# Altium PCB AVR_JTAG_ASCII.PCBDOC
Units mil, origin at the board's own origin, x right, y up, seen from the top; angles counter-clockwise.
Board outline 2025 x 2150 mil, 2 copper layers (Top Layer, Bottom Layer); 21 components, 27 nets, 110 pads, 2 vias.
Unrouted connection lines stored in the file: 1.
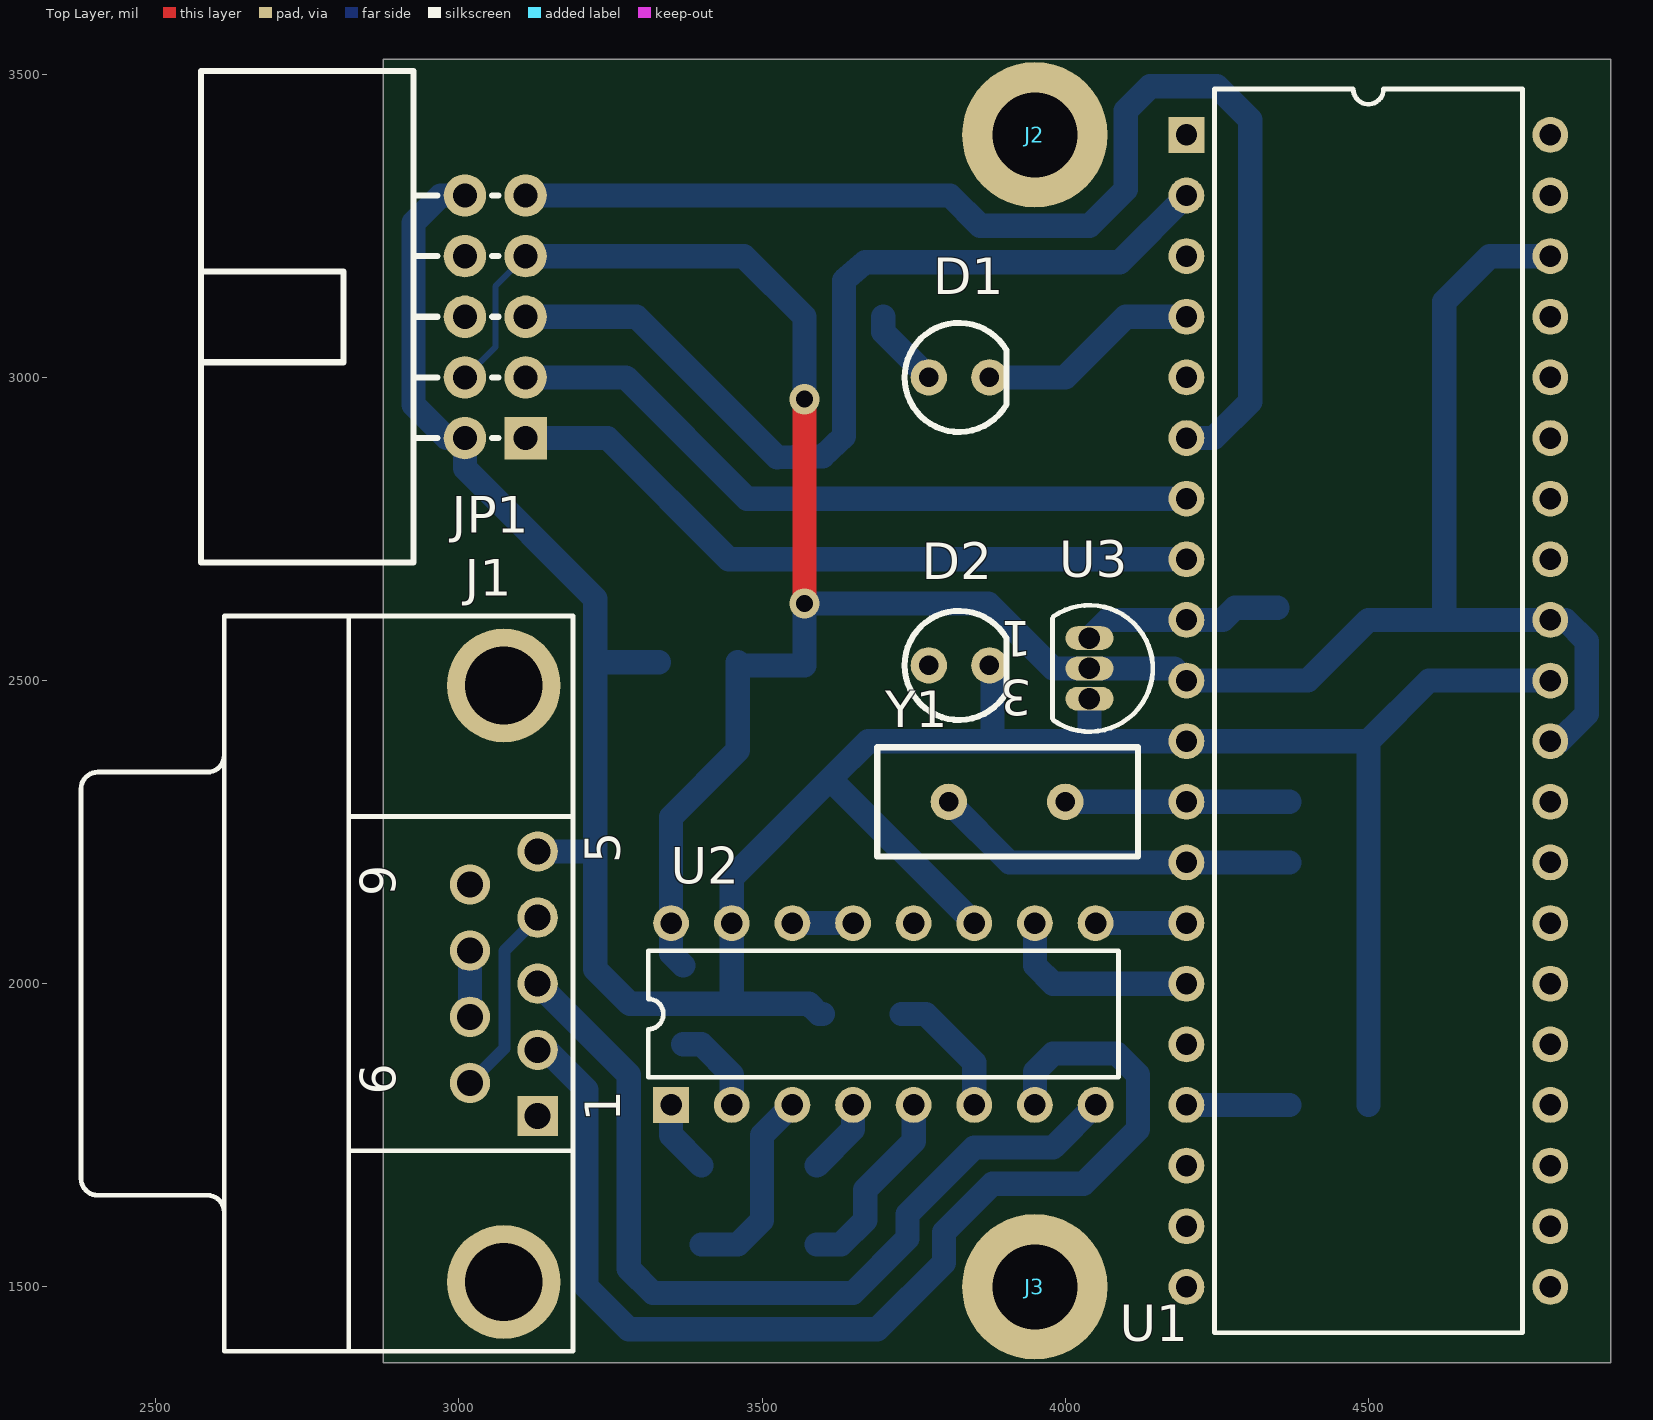
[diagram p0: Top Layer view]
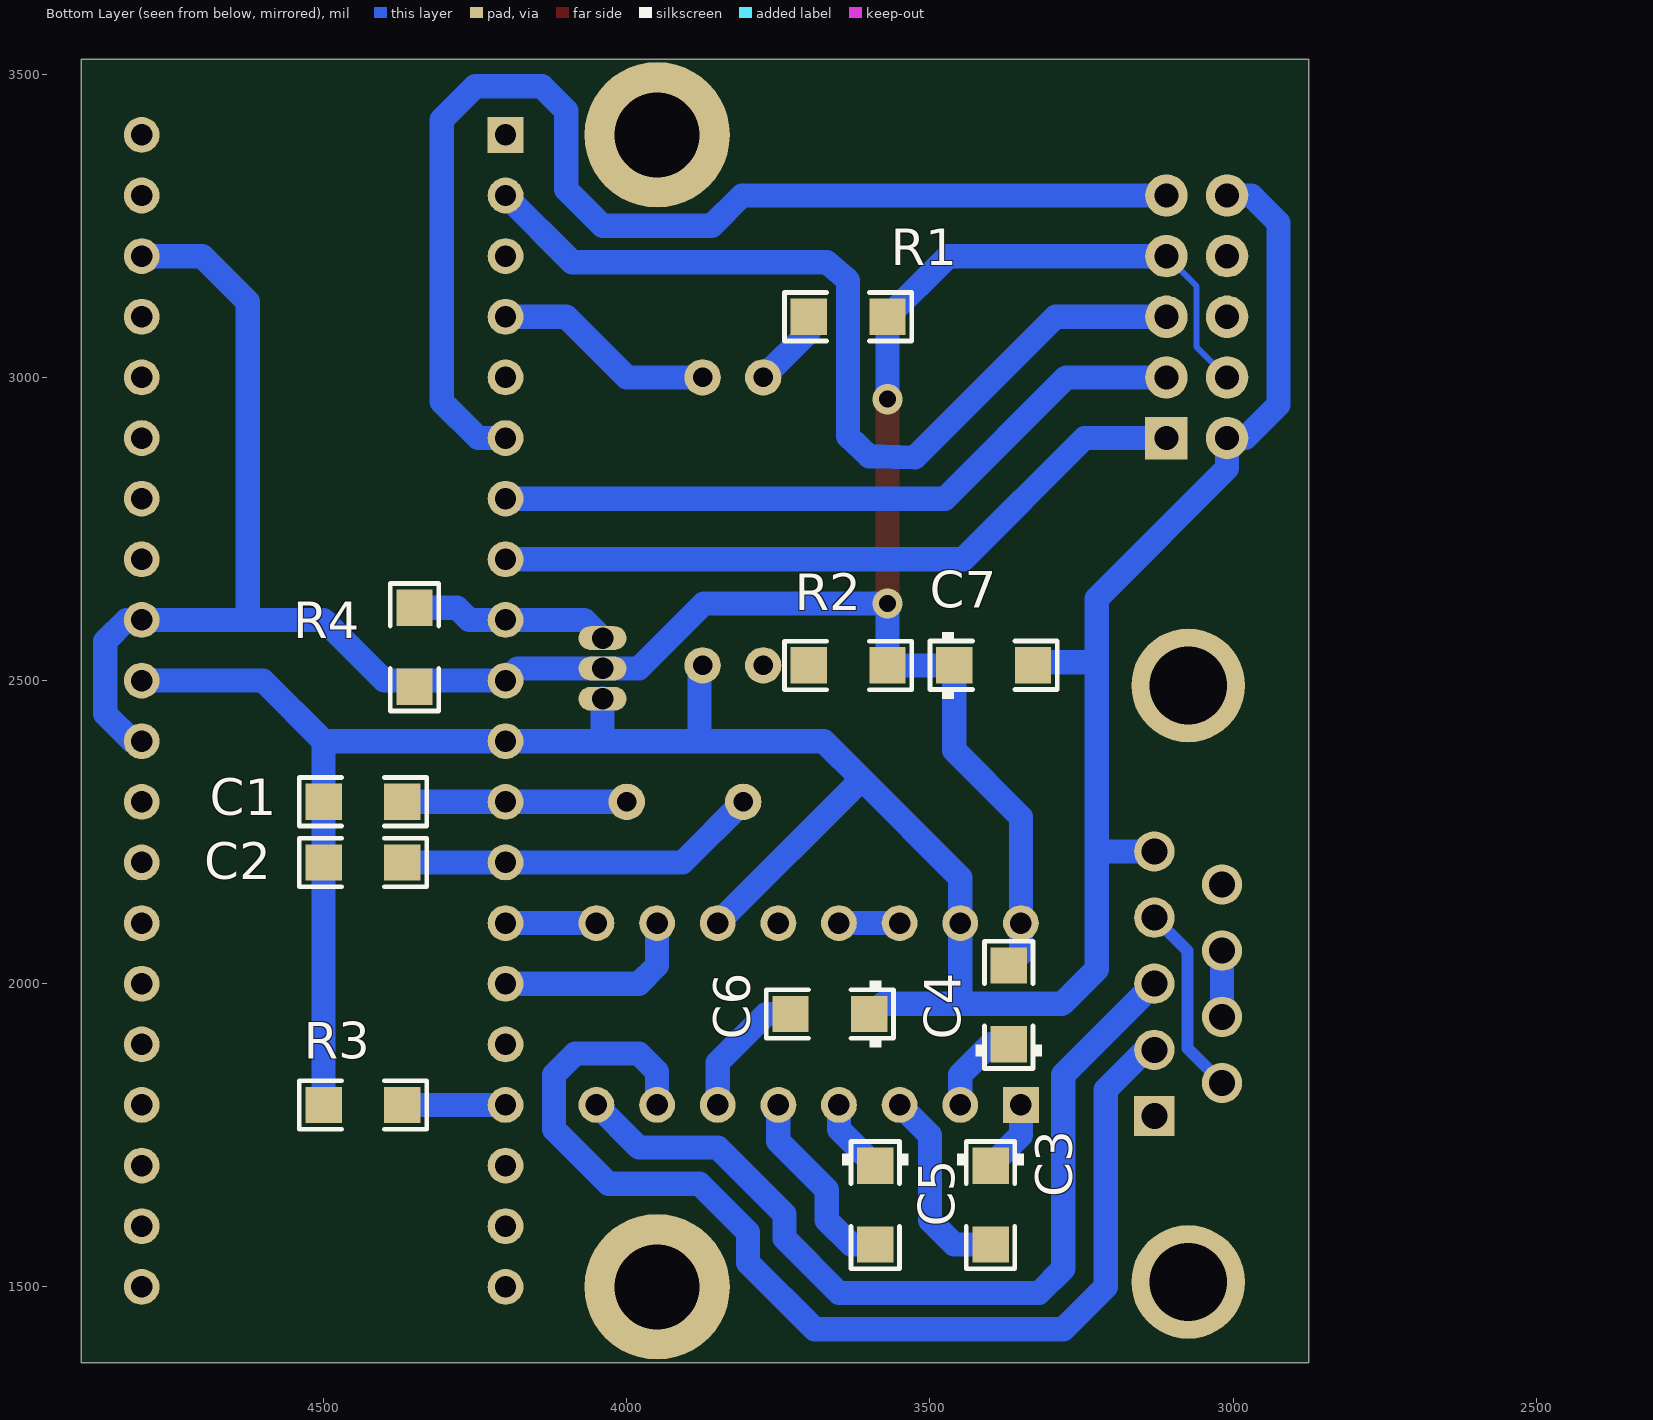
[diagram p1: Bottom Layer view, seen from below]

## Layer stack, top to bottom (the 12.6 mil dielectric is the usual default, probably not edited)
Top Layer: signal copper 1.4
Dielectric: dielectric 12.6, FR-4, Dk 4.8
Bottom Layer: signal copper 1.4

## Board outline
2875,1375 2875,3525 4900,3525 4900,1375

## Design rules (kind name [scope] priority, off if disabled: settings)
Clearance [All] p1: scope1count=1 scope1_0_kind=Board scope1_0_value=Board scope2count=1 scope2_0_kind=Board scope2_0_value=Board commentlength=0 planeconnectstyle=Relief reliefexpansion=20 reliefentries=4 reliefconductorwidth=10 reliefairgap="10mil / RECORD=DXPRule" gap=10
ComponentClearance [All] p1: scope1count=1 scope1_0_kind=Board scope1_0_value=Board scope2count=1 scope2_0_kind=Board scope2_0_value=Board commentlength=0 enforce="TRUE / RECORD=DXPRule" gap=10 collisioncheckmode=1
LayerPairs [All] p1: scope1count=1 scope1_0_kind=Board scope1_0_value=Board scope2count=1 scope2_0_kind=Board scope2_0_value=Board commentlength=0 absolutevalues=TRUE maxlimit=100 minlimit=1 maxpercent=80.000 minpercent="20.000 / RECORD=DXPRule" enforce=TRUE
PasteMaskExpansion [All] p1: scope1count=1 scope1_0_kind=Board scope1_0_value=Board scope2count=1 scope2_0_kind=Board scope2_0_value=Board commentlength=0 expansion=0
PlaneClearance [All] p1: scope1count=1 scope1_0_kind=Board scope1_0_value=Board scope2count=1 scope2_0_kind=Board scope2_0_value=Board commentlength=0 connectstyle=Relief reliefconductorwidth=10 reliefentries=4 polygonreliefangle="90 Angle / RECORD=DXPRule" clearance=20
PlaneConnect [All] p1: scope1count=1 scope1_0_kind=Board scope1_0_value=Board scope2count=1 scope2_0_kind=Board scope2_0_value=Board commentlength=0 clearance="20mil / RECORD=DXPRule" planeconnectstyle=Relief reliefexpansion=20 reliefentries=4 reliefconductorwidth=10 reliefairgap=10
PolygonConnect [All] p1: scope1count=1 scope1_0_kind=Board scope1_0_value=Board scope2count=1 scope2_0_kind=Board scope2_0_value=Board commentlength=0 maxlimit=40 minlimit=10 preferedwidth="40mil / RECORD=DXPRule" connectstyle=Relief reliefconductorwidth=10 reliefentries=4 polygonreliefangle="90 Angle"
RoutingCorners [All] p1: scope1count=1 scope1_0_kind=Board scope1_0_value=Board scope2count=1 scope2_0_kind=Board scope2_0_value=Board commentlength=0 holewidth=28 width=50 viastyle="Through Hole" minholewidth=28 minwidth=50 maxholewidth=28 maxwidth="50mil / RECORD=DXPRule" cornerstyle=45-Degree minsetback=100 maxsetback=100
RoutingLayers [All] p1: scope1count=1 scope1_0_kind=Board scope1_0_value=Board scope2count=1 scope2_0_kind=Board scope2_0_value=Board commentlength=0 cornerstyle=45-Degree minsetback=100 maxsetback="100mil / RECORD=DXPRule" top layer=Horizontal bottom layer=Vertical
RoutingPriority [All] p1: scope1count=1 scope1_0_kind=Board scope1_0_value=Board scope2count=1 scope2_0_kind=Board scope2_0_value=Board commentlength=0 top layer=Horizontal bottom layer="Vertical / RECORD=DXPRule" routingpriority=0
RoutingTopology [All] p1: scope1count=1 scope1_0_kind=Board scope1_0_value=Board scope2count=1 scope2_0_kind=Board scope2_0_value=Board commentlength=0 valid=0 allowmultiple="FALSE / RECORD=DXPRule" topology=Shortest
RoutingVias [All] p1: scope1count=1 scope1_0_kind=Board scope1_0_value=Board scope2count=1 scope2_0_kind=Board scope2_0_value=Board commentlength=0 expansion="0mil / RECORD=DXPRule" holewidth=28 width=50 viastyle="Through Hole" minholewidth=28 minwidth=50 maxholewidth=28 maxwidth=50
ShortCircuit [All] p0: scope1count=1 scope1_0_kind=Board scope1_0_value=Board scope2count=1 scope2_0_kind=Board scope2_0_value=Board commentlength=0 allowed=FALSE
ShortCircuit [All] p1: scope1count=1 scope1_0_kind=Board scope1_0_value=Board scope2count=1 scope2_0_kind=Board scope2_0_value=Board commentlength=0 allowed=FALSE
SolderMaskExpansion [All] p1: scope1count=1 scope1_0_kind=Board scope1_0_value=Board scope2count=1 scope2_0_kind=Board scope2_0_value=Board commentlength=0 topology="Shortest / RECORD=DXPRule" expansion=4
TestPointUsage [All] p1: scope1count=1 scope1_0_kind=Board scope1_0_value=Board scope2count=1 scope2_0_kind=Board scope2_0_value=Board commentlength=0 side=15 testpointundercomponent=TRUE minsize=40 maxsize=100 preferedsize=60 minholesize=0 maxholesize=40 preferedholesize=32 testpointgrid=1 style=1023 order="1234567890 / RECORD=DXPRule" valid=0 allowmultiple=FALSE
Testpoint [All] p1: scope1count=1 scope1_0_kind=Board scope1_0_value=Board scope2count=1 scope2_0_kind=Board scope2_0_value=Board commentlength=0 gap=10 collisioncheckmode="1 / RECORD=DXPRule" side=15 testpointundercomponent=TRUE minsize=40 maxsize=100 preferedsize=60 minholesize=0 maxholesize=40 preferedholesize=32 testpointgrid=1 style=1023 order=1234567890
UnRoutedNet [All] p1: scope1count=1 scope1_0_kind=Board scope1_0_value=Board scope2count=1 scope2_0_kind=Board scope2_0_value=Board commentlength=0 gap="10mil / RECORD=DXPRule"
Width [All] p1: scope1count=1 scope1_0_kind=Board scope1_0_value=Board scope2count=1 scope2_0_kind=Board scope2_0_value=Board commentlength=0 maxlimit=40 minlimit=10 preferedwidth=40

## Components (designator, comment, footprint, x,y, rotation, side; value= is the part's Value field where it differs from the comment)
C1 "" SMD1206 4500,2300 r180 bottom
C2 "" SMD1206 4500,2200 r180 bottom
C3 "" "SMD1206 POL" 3400,1700 r270 bottom
C4 "" "SMD1206 POL" 3370,1900 r90 bottom
C5 "" "SMD1206 POL" 3590,1700 r270 bottom
C6 "" "SMD1206 POL" 3600,1950 r0 bottom
C7 "" "SMD1206 POL" 3460,2525 r180 bottom
D1 "" "LED 3MM" 3825,3000 r0 top
D2 "" "LED 3mm" 3825,2525 r0 top
J1 "D Connector 9" DSUB9F90 2830,2400 r180 top
J2 "M3 csavar" "M3 CSAVAR"#1 11472,1174 r90 top locked
J3 "M3 csavar" "M3 CSAVAR"#2 11174,1174 r90 top locked
JP1 "" MLW10A 3110,2900 r90 top
R1 "" SMD1206 3570,3100 r0 bottom
R2 "" SMD1206 3700,2525 r180 bottom
R3 "" SMD1206 4500,1800 r180 bottom
R4 "" SMD1206 4350,2620 r270 bottom
U1 "ATMEGA163-8AI" DIP-40 4500,2450 r270 top
U2 "MAX232ACPE" DIP-16/X1.5 3700,1950 r0 top
U3 "MC33064P-5" BCY-W3 4040,2520 r180 top
Y1 "XTAL" XTAL 4000,2300 r180 top

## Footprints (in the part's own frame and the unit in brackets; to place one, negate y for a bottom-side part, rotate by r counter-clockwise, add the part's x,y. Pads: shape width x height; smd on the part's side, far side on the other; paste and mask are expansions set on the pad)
BCY-W3 [mm]
  oval 2x1 hole 0.9: 1(0,-1.27) 2(0,0) 3(0,1.27)
  silkscreen extent -2.65,-2.65 1.55,2.65
DIP-16/X1.5 [mm]
  rect 1.5x1.5 hole 0.9: 1(-8.89,-3.81)
  round 1.5 hole 0.9: 2(-6.35,-3.81) 3(-3.81,-3.81) 4(-1.27,-3.81) 5(1.27,-3.81) 6(3.81,-3.81) 7(6.35,-3.81) 8(8.89,-3.81) 9(8.89,3.81) 10(6.35,3.81) 11(3.81,3.81) 12(1.27,3.81) 13(-1.27,3.81) 14(-3.81,3.81) 15(-6.35,3.81) 16(-8.89,3.81)
  silkscreen extent -9.85,-2.65 9.85,2.65
DIP-40 [mm]
  rect 1.5x1.5 hole 0.9: 1(-24.13,-7.62)
  round 1.5 hole 0.9: 2(-21.59,-7.62) 3(-19.05,-7.62) 4(-16.51,-7.62) 5(-13.97,-7.62) 6(-11.43,-7.62) 7(-8.89,-7.62) 8(-6.35,-7.62) 9(-3.81,-7.62) 10(-1.27,-7.62) 11(1.27,-7.62) 12(3.81,-7.62) 13(6.35,-7.62) 14(8.89,-7.62) 15(11.43,-7.62) 16(13.97,-7.62) 17(16.51,-7.62) 18(19.05,-7.62) 19(21.59,-7.62) 20(24.13,-7.62) 21(24.13,7.62) 22(21.59,7.62) 23(19.05,7.62) 24(16.51,7.62) 25(13.97,7.62) 26(11.43,7.62) 27(8.89,7.62) 28(6.35,7.62) 29(3.81,7.62) 30(1.27,7.62) 31(-1.27,7.62) 32(-3.81,7.62) 33(-6.35,7.62) 34(-8.89,7.62) 35(-11.43,7.62) 36(-13.97,7.62) 37(-16.51,7.62) 38(-19.05,7.62) 39(-21.59,7.62) 40(-24.13,7.62)
  silkscreen extent -26.05,-6.45 26.05,6.45
DSUB9F90 [mm]
  rect 1.69x1.69 hole 1.09: 1(-7.62,15.7)
  round 1.69 hole 1.09: 2(-7.62,12.93) 3(-7.62,10.16) 4(-7.62,7.39) 5(-7.62,4.62) 6(-4.78,14.315) 7(-4.78,11.545) 8(-4.78,8.775) 9(-4.78,6.005)
  round 4.76 hole 3.26: 10(-6.2,22.655) 11(-6.2,-2.335)
  silkscreen extent -9.1,-5.24 11.51,25.56
"LED 3MM" [mil]
  round 60 hole 32: 1(-50,0) 2(50,0)
  silkscreen extent -90,-90 78,90
"LED 3mm" [mil]
  round 60 hole 32: 1(-50,0) 2(50,0)
  silkscreen extent -90,-90 78,90
"M3 CSAVAR"#1 [mil]
  round 240 hole 140: 1(2226,7522)
"M3 CSAVAR"#2 [mil]
  round 240 hole 140: 1(326,7224)
MLW10A [mil]
  rect 70x70 hole 40: 1(0,0)
  round 70 hole 40: 2(0,100) 3(100,0) 4(100,100) 5(200,0) 6(200,100) 7(300,0) 8(300,100) 9(400,0) 10(400,100)
  silkscreen extent -205,45 605,535
SMD1206 [mil]
  rect 60x60 smd: 1(0,0) 2(130,0)
  silkscreen extent -40,-40 170,40
"SMD1206 POL" [mil]
  rect 60x60 smd: 1(0,0) 2(130,0)
  silkscreen extent -40,-55 170,55
XTAL [mil]
  round 60 hole 32: 1(0,0) 2(192,0)
  silkscreen extent -120,-90 310,90

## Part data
C1 C2: library part CAPSMD, "Capacitor SMD1206"
C3 C4 C5 C6 C7: library part CAPPOLSMD, "Capacitor Polarity SMD1206"
D1: library part "LED Piros", "Piros Led 3mm"
D2: library part "LED Zöld", "Zöld Led 3mm"
J1: "Receptacle Assembly, 9 Position, Right Angle"
J2 J3: library part "M3 CSAVAR", "M3 csavar hely"
JP1: library part MLW10A, "Header, 5-Pin, Dual row, Right Angle"
R1 R2 R3 R4: library part RES, "Resistor SMD1206, 1% fémréteg"
U1: "8 bit microcontroller"
U2: "+5V Powered, Multi-Channel RS-232 Driver/Receiver"
U3: "Undervoltage Sensing Circuit"
Y1: "Crystal Oscillator"

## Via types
v1: diameter 50, hole 28, Top Layer to Bottom Layer, 2 vias

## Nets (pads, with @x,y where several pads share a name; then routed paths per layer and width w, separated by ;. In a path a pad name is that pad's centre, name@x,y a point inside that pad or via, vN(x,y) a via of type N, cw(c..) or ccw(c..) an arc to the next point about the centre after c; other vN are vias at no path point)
GND: C1.1 C2.1 C6.1 C7.2 D2.2 J1.5 JP1.2 JP1.10 R3.1 U1.11 U1.31 U2.11 U2.15 U3.3 | length 4902.1
  Bottom Layer w40: JP1.10 2970,3300 2925,3255 2925,2955 2980,2900 JP1.2 3010,2850 3225,2635 3225,2024 3282,1967 3577,1967 3594,1950 C6.1 ; J1.5@3129.92,2218.11 J1.5 3224.89,2218.11 ; 3227,2530 C7.2@3330,2530 ; 3450,1969 U2.15 3450,2175 3613.41,2338.41 ; U2.11 3613.41,2336.59 3613.41,2338.41 ; D2.2@3880,2525 3880,2400 ; U3.3 4040,2400 ; R3.1 C2.1 C1.1 4500,2400 ; U1.31 4600,2500 4500,2400 ; 3613.41,2338.41 3675,2400 3880,2400 ; 3880,2400 4040,2400 ; 4040,2400 U1.11 4500,2400
NetC1_2: C1.2 U1.12 Y1.1 | length 370
  Bottom Layer w40: Y1.1 U1.12 C1.2
NetC2_2: C2.2 U1.13 Y1.2 | length 603.4
  Bottom Layer w40: Y1.2 3908,2200 U1.13 C2.2
NetC3_1: C3.1 U2.1 | length 120.7
  Bottom Layer w40: U2.1 3350,1750 C3.1
NetC3_2: C3.2 U2.3 | length 327.3
  Bottom Layer w40: C3.2 3460,1570 3500,1610 3500,1750 U2.3
NetC4_1: C4.1 U2.2 | length 150.7
  Bottom Layer w40: C4.1 3400,1900 3450,1850 U2.2
NetC5_1: C5.1 U2.4 | length 124.9
  Bottom Layer w40: C5.1 3650,1760 U2.4
NetC5_2: C5.2 U2.5 | length 319.7
  Bottom Layer w40: C5.2 3630,1570 3670,1610 3670,1660 3750,1740 U2.5
NetC6_2: C6.2 U2.6 | length 223.1
  Bottom Layer w40: C6.2 3770,1950 3850,1870 U2.6
NetD1_1: D1.1 R1.2 | length 131.1
  Bottom Layer w40: R1.2 3700,3075 D1.1
NetD1_2: D1.2 U1.4 | length 366.4
  Bottom Layer w40: D1.2 4000,3000 4100,3100 U1.4
NetD2_1: D2.1 R2.1
NetJ1_2: J1.2 U2.7 | length 1879.3
  Bottom Layer w40: J1.2@3129.92,1890.94 J1.2 3144.06,1890.94 3210,1825 3210,1500 3280,1430 3690,1430 3800,1540 3800,1590 3880,1670 4030,1670 4120,1760 4120,1850 4085,1885 3980,1885 3950,1855 U2.7
NetJ1_3: J1.3 U2.8 | length 1470.6
  Bottom Layer w40: J1.3@3129.92,2000 J1.3 3280,1849.92 3280,1530 3320,1490 3650,1490 3740,1580 3740,1620 3850,1730 3980,1730 U2.8
NetJ1_4: J1.4 J1.6 | length 319
  Bottom Layer w20: J1.6@3018.11,1836.42 3018.15,1836.46 3075,1893.31 3075,2054.13 J1.4@3129.92,2109.05
NetJ1_7: J1.7 J1.8 | length 109.1
  Bottom Layer w40: J1.7@3018.11,1945.47 J1.8@3018.11,2054.53
NetR3_2: R3.2 U1.17 | length 170
  Bottom Layer w40: U1.17 R3.2
NetR4_1: R4.1 U1.9 U3.1 | length 330.7
  Bottom Layer w40: U3.1 4070,2600 U1.9 4260,2600 4280,2620 R4.1
NetU1_14: U1.14 U2.9 | length 150
  Bottom Layer w40: U2.9 U1.14
NetU1_15: U1.15 U2.10 | length 332.4
  Bottom Layer w40: U2.10 3950,2030 3980,2000 U1.15
NetU2_12: U2.12 | length 6
  Bottom Layer w40: U2.12@3751,2092 U2.12@3751,2098
NetU2_13: U2.13 U2.14 | length 100
  Bottom Layer w40: U2.14 U2.13
TCK: JP1.1 U1.8 | length 1172.8
  Bottom Layer w40: JP1.1 3245,2900 3445,2700 U1.8
TDI: JP1.9 U1.6 | length 2004.8
  Bottom Layer w40: JP1.9 3810,3300 3860,3250 4040,3250 4100,3310 4100,3440 4140,3480 4250,3480 4305,3425 4305,2960 4245,2900 U1.6
TDO: JP1.3 U1.7 | length 1172.8
  Bottom Layer w40: JP1.3 3275,3000 3475,2800 U1.7
TMS: JP1.5 U1.2 | length 1512.9
  Bottom Layer w40: JP1.5 3293,3100 3525,2868 3600,2870 3635,2903 3635,3160 3670,3190 4090,3190 U1.2
VCC: C4.2 C7.1 JP1.4 JP1.7 R1.1 R2.2 R4.2 U1.10 U1.30 U1.32 U1.38 U2.16 U3.2 | length 4312
  Top Layer w40: v1(3570,2627) v1(3570,2964)
  Bottom Layer w10: JP1.4 3060,3050 3060,3150 JP1.7
  Bottom Layer w40: JP1.7 3470,3200 R1.1 v1(3570,2964) ; C4.2 3350,2050 U2.16 3350,2275 3460,2385 C7.1 3460,2530 3462.5,2527.5 3465,2525 R2.2 v1(3570,2627) 3873,2627 3980,2520 U3.2 4180,2520 U1.10 4350,2500 4400,2500 4500,2600 4625,2600 ; U1.30 4815,2400 4860,2445 4860,2565 4825,2600 U1.32 4625,2600 ; U1.38 4700,3200 4625,3125 4625,2600
pads on no net: J1.1 J1.9 J1.10 J1.11 J2.1 J3.1 JP1.6 JP1.8 U1.1 U1.3 U1.5 U1.16 U1.18 U1.19 U1.20 U1.21 U1.22 U1.23 U1.24 U1.25 U1.26 U1.27 U1.28 U1.29 U1.33 U1.34 U1.35 U1.36 U1.37 U1.39 U1.40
